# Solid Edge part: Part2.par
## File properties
Author: Robert a Rhodes jr
Template: Normal.par
Last saved by: Cadcim
Revision: 5
Application: Solid Edge
Accuracy: 0.99
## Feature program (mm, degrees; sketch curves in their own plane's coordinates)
sketch for "unnamed Protrusion 1" plane through (0, 0, 0) normal (0, 0, 1) x-axis (1, 0, 0)
  circle centre (0, 0) radius 7
extrude "unnamed Protrusion 1" add finite 13 along +normal
sketch for "ExtrudedProtrusion_2" plane through (0, 0, 13) normal (0, 0, 1) x-axis (0, 1, 0)
  circle centre (0, 0) radius 8.8981
extrude "ExtrudedProtrusion_2" add finite 60.325 along +normal
sketch for "ExtrudedProtrusion_3" plane through (0, 0, 73.325) normal (0, 0, 1) x-axis (0, 1, 0)
  circle centre (0, 0) radius 7
extrude "ExtrudedProtrusion_3" add finite 13 along +normal
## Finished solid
Body 1: solid body, 7 faces, 6 edges, 0 vertices.
  Faces by surface: plane 4, cylinder 3
  Edges by curve: circle 6
Bounding box of the edges (mm): 17.796 x 17.796 x 86.325, from (-8.8981, -8.8981, 0) to (8.8981, 8.8981, 86.325).
Cylindrical faces by radius (mm): R7 x2, R8.8981 x1
Planar faces by outward normal: +z 2, -z 2
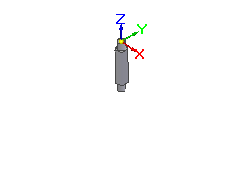
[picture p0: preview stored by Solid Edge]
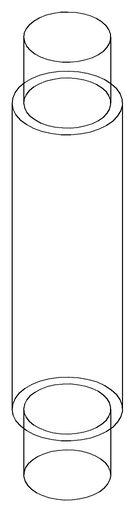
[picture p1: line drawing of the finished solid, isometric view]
